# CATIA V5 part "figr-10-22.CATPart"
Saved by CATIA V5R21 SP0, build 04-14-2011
Part number: Part1
Bounding box of the stored display mesh (mm): x -174.518 to 0, y -36.805 to 36.805, z 0 to 36.805
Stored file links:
  D:\CATIA V5R21 E-RESOURCES\CATIA-V5R21\catia-v5r21-prt\c10-catia-v5r20-prt\c10-catia-v5r21-figr-10-22.CATPart
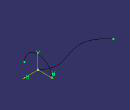
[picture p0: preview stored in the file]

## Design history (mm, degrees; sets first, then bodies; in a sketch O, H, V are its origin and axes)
Body1 (main body)
  Sketch1 on xy-plane, origin (0, 0, 0), H (1, 0, 0), V (0, 1, 0)
    spline S1 through (0, 0) (-31.5913, 14.7273) (-94.8038, 0) (-174.5181, 29.5113)
    point P1 (0, 0)
    point P2 (-94.8038, 0)
    coincidence: P1 O, P2 H
  Sketch2 on yz-plane, origin (0, 0, 0), H (0, 1, 0), V (0, 0, 1)
    arc A1 centre (0, 0) radius 36.8048 from (36.8048, 0) to (-36.8048, 0) ccw
    point P1 (-36.8048, 0)
    point P2 (36.8048, 0)
    coincidence: P1 H, P2 H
